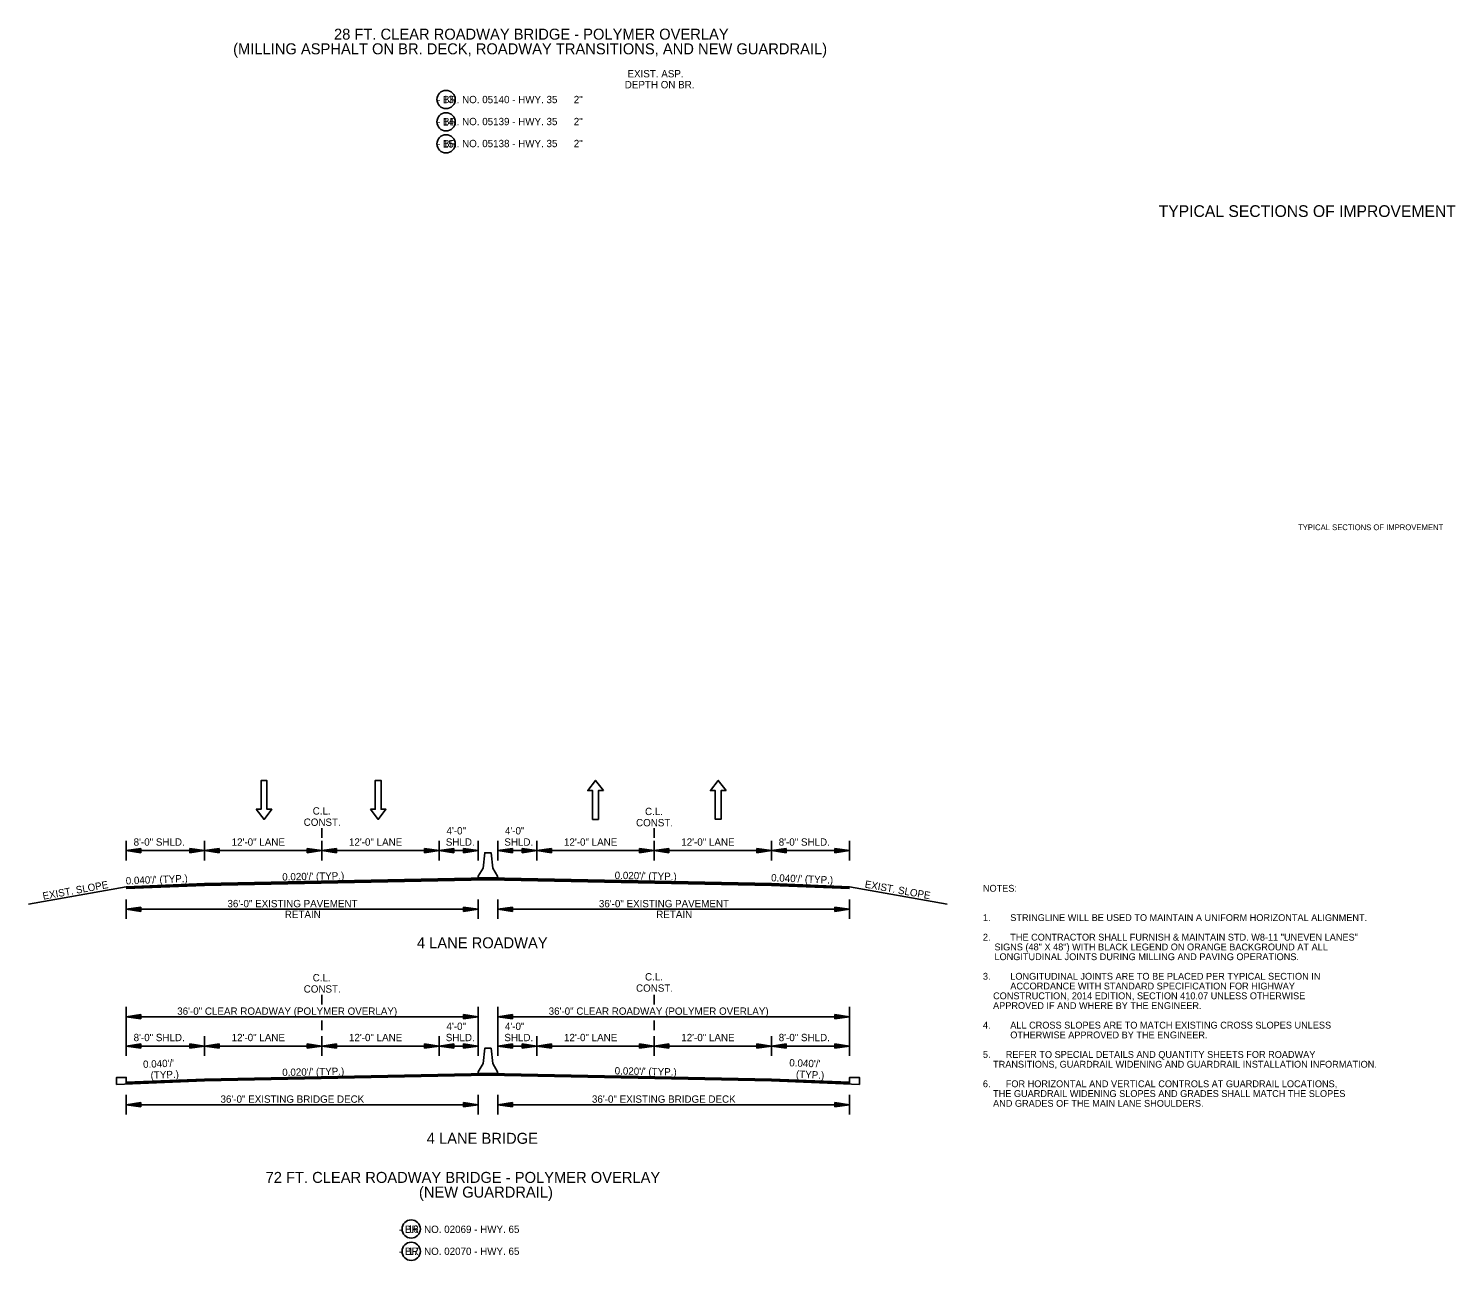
# Model space of a CAD drawing. Extents: x 545241 to 1930787, y -1971772 to 596640.
# Drawn here: x 546808 to 548268, y -1954639 to -1953379 of the extents above; entities that cross this region are included whole.
import ezdxf

# ---------------------------------------------------------------- set-up
doc = ezdxf.new("R2010")
doc.units = 0
for name, color, linetype in [('Default', 7, 'Continuous'), ('R_Border', 7, 'Continuous'), ('R_Border Notes', 7, 'Continuous'), ('R_Border Prem', 7, 'Continuous'), ('R_Draft', 7, 'Continuous')]:
    doc.layers.add(name, color=color, linetype=linetype)

# ---------------------------------------------------------------- blocks, each defined once
blk = doc.blocks.new('ARROW')
at = {"layer": 'R_Draft'}
for p, q in [((-2, 0.3), (0, 0)), ((-2, 0.3), (-2, -0.3)), ((-2, 0.25), (-0.334, 0)), ((-2, 0.199), (-0.678, 0)), ((-2, 0.149), (-1.011, 0)), ((-2, 0.097), (-1.35, 0)), ((-2, 0.047), (-1.684, 0)), ((-2, -0.3), (0, 0)), ((-2, -0.098), (-1.35, 0)), ((-2, -0.199), (-0.678, 0)), ((-2, -0.25), (-0.334, 0)), ((-2, -0.149), (-1.011, 0)), ((-2, -0.047), (-1.684, 0))]:
    blk.add_line(p, q, dxfattribs=at)
blk = doc.blocks.new('MedBarrier')
at = {"layer": 'Default'}
blk.add_lwpolyline([(-10, 0), (-9.9, 1.7), (-5, 10), (-3.3, 25.8), (3.3, 25.8), (5, 10), (9.9, 1.7), (10, 0)], close=True, dxfattribs=at)

msp = doc.modelspace()

# ---------------------------------------------------------------- linework, layer by layer
at = {"layer": 'R_Border'}
for p, q in [((547108, -1954196.8), (547108, -1954206.8)), ((547448, -1954196.8), (547448, -1954206.8)), ((546908, -1954209.8), (546908, -1954229.8)), ((546988, -1954209.8), (546988, -1954229.8)), ((547108, -1954209.8), (547108, -1954229.8)), ((547228, -1954209.8), (547228, -1954229.8)), ((547268, -1954209.8), (547268, -1954229.8)), ((547288, -1954209.8), (547288, -1954229.8)), ((547328, -1954209.8), (547328, -1954229.8)), ((547448, -1954209.8), (547448, -1954229.8)), ((547568, -1954209.8), (547568, -1954229.8)), ((547648, -1954209.8), (547648, -1954229.8)), ((546908, -1954219.8), (547268, -1954219.8)), ((547288, -1954219.8), (547648, -1954219.8)), ((546908, -1954256.8), (546808, -1954274.8)), ((547648, -1954256.8), (547748, -1954274.8)), ((546908, -1954269.8), (546908, -1954289.8)), ((547268, -1954269.8), (547268, -1954289.8)), ((547288, -1954269.8), (547288, -1954289.8)), ((547648, -1954269.8), (547648, -1954289.8)), ((546908, -1954279.8), (547268, -1954279.8)), ((547288, -1954279.8), (547648, -1954279.8)), ((547108, -1954367.3), (547108, -1954377.3)), ((547448, -1954367.3), (547448, -1954377.3)), ((546908, -1954379.8), (546908, -1954429.8)), ((546908, -1954389.8), (547268, -1954389.8)), ((547268, -1954379.8), (547268, -1954429.8)), ((547288, -1954379.8), (547288, -1954429.8)), ((547288, -1954389.8), (547648, -1954389.8)), ((547648, -1954379.8), (547648, -1954429.8)), ((547108, -1954393.5), (547108, -1954403.6)), ((547448, -1954393.5), (547448, -1954403.6)), ((546908, -1954419.8), (547268, -1954419.8)), ((546988, -1954409.8), (546988, -1954429.8)), ((547108, -1954409.8), (547108, -1954429.8)), ((547228, -1954409.8), (547228, -1954429.8)), ((547288, -1954419.8), (547648, -1954419.8)), ((547328, -1954409.8), (547328, -1954429.8)), ((547448, -1954409.8), (547448, -1954429.8)), ((547568, -1954409.8), (547568, -1954429.8)), ((546908, -1954469.8), (546908, -1954489.8)), ((546908, -1954469.8), (546908, -1954489.8)), ((547268, -1954469.8), (547268, -1954489.8)), ((547288, -1954469.8), (547288, -1954489.8)), ((547648, -1954469.8), (547648, -1954489.8)), ((547648, -1954469.8), (547648, -1954489.8)), ((546908, -1954479.8), (547268, -1954479.8)), ((547288, -1954479.8), (547648, -1954479.8))]:
    msp.add_line(p, q, dxfattribs=at)
for points in [[(547040.9, -1954177.6), (547048.9, -1954188), (547056.9, -1954177.6), (547051.9, -1954177.6), (547051.9, -1954148.2), (547045.9, -1954148.2), (547045.9, -1954177.6)], [(547157.7, -1954177.6), (547165.7, -1954187.9), (547173.7, -1954177.6), (547168.7, -1954177.6), (547168.7, -1954148.1), (547162.7, -1954148.1), (547162.7, -1954177.6)], [(547396.1, -1954158.5), (547388.1, -1954148.1), (547380.1, -1954158.5), (547385.1, -1954158.5), (547385.1, -1954187.9), (547391.1, -1954187.9), (547391.1, -1954158.5)], [(547521.6, -1954158.4), (547513.6, -1954148), (547505.6, -1954158.4), (547510.6, -1954158.4), (547510.6, -1954187.8), (547516.6, -1954187.8), (547516.6, -1954158.4)]]:
    msp.add_lwpolyline(points, close=True, dxfattribs=at)
for points in [[(546908, -1954256.8), (546988, -1954253.6), (547278, -1954247.8), (547568, -1954253.6), (547648, -1954256.8)], [(546908, -1954257.1), (546988, -1954253.9), (547278, -1954248.1), (547568, -1954253.9), (547648, -1954257.1)], [(546908, -1954257.4), (546988, -1954254.2), (547278, -1954248.4), (547568, -1954254.2), (547648, -1954257.4)], [(546908, -1954257.7), (546988, -1954254.5), (547278, -1954248.7), (547568, -1954254.5), (547648, -1954257.7)], [(546908, -1954258), (546988, -1954254.8), (547278, -1954249), (547568, -1954254.8), (547648, -1954258)], [(546908, -1954258.3), (546988, -1954255.1), (547278, -1954249.3), (547568, -1954255.1), (547648, -1954258.3)], [(546908, -1954258.6), (546988, -1954255.4), (547278, -1954249.6), (547568, -1954255.4), (547648, -1954258.6)], [(546908, -1954456.8), (546988, -1954453.6), (547278, -1954447.8), (547568, -1954453.6), (547648, -1954456.8)], [(546908, -1954457.1), (546988, -1954453.9), (547278, -1954448.1), (547568, -1954453.9), (547648, -1954457.1)], [(546908, -1954457.4), (546988, -1954454.2), (547278, -1954448.4), (547568, -1954454.2), (547648, -1954457.4)], [(546908, -1954457.7), (546988, -1954454.5), (547278, -1954448.7), (547568, -1954454.5), (547648, -1954457.7)], [(546908, -1954458), (546988, -1954454.8), (547278, -1954449), (547568, -1954454.8), (547648, -1954458)], [(546908, -1954458.3), (546988, -1954455.1), (547278, -1954449.3), (547568, -1954455.1), (547648, -1954458.3)], [(546898, -1954459), (546988, -1954455.4), (547278, -1954449.6), (547568, -1954455.4), (547658, -1954459)], [(546908, -1954458.3), (546908, -1954451.8), (546898, -1954451.8), (546898, -1954459)], [(547648, -1954459), (547648, -1954451.8), (547658, -1954451.8), (547658, -1954459)]]:
    msp.add_lwpolyline(points, dxfattribs=at)
for centre in [(547235.2, -1953451.4), (547235.2, -1953474.3), (547235.2, -1953496.8), (547199.5, -1954607), (547199.5, -1954629.8)]:
    msp.add_circle(centre, 9.34, dxfattribs=at)

# ---------------------------------------------------------------- block references
at = {"layer": 'R_Border', "xscale": 7.5, "yscale": 7.5, "rotation": 180}
for p in [(546908, -1954219.8), (546988, -1954219.8), (546988, -1954219.8), (547108, -1954219.8), (547228, -1954219.8), (547288, -1954219.8), (547328, -1954219.8), (547448, -1954219.8), (547568, -1954219.8), (546908, -1954279.8), (547288, -1954279.8), (546908, -1954389.8), (547288, -1954389.8), (546908, -1954419.8), (546988, -1954419.8), (546988, -1954419.8), (547108, -1954419.8), (547228, -1954419.8), (547288, -1954419.8), (547328, -1954419.8), (547448, -1954419.8), (547568, -1954419.8), (546908, -1954479.8), (546908, -1954479.8), (547288, -1954479.8)]:
    msp.add_blockref('ARROW', p, dxfattribs=at)
at = {"layer": 'R_Border', "xscale": 7.5, "yscale": 7.5}
for p in [(546988, -1954219.8), (547108, -1954219.8), (547228, -1954219.8), (547268, -1954219.8), (547328, -1954219.8), (547448, -1954219.8), (547568, -1954219.8), (547648, -1954219.8), (547268, -1954279.8), (547648, -1954279.8), (547268, -1954389.8), (547648, -1954389.8), (546988, -1954419.8), (547108, -1954419.8), (547228, -1954419.8), (547268, -1954419.8), (547328, -1954419.8), (547448, -1954419.8), (547568, -1954419.8), (547648, -1954419.8), (547268, -1954479.8), (547648, -1954479.8), (547648, -1954479.8)]:
    msp.add_blockref('ARROW', p, dxfattribs=at)
at = {"layer": 'R_Draft', "rotation": 0.0005105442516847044}
for p in [(547278, -1954247.8), (547278, -1954447.8)]:
    msp.add_blockref('MedBarrier', p, dxfattribs=at)

# ---------------------------------------------------------------- texts
at = {"layer": 'R_Border'}
for s, height, p in [('28 FT. CLEAR ROADWAY BRIDGE - POLYMER OVERLAY', 11.25, (547120.5, -1953390.2)), ('(MILLING ASPHALT ON BR. DECK, ROADWAY TRANSITIONS, AND NEW GUARDRAIL)', 11.25, (547017.3, -1953405.2)), ('13', 7.5, (547231.9, -1953455.1)), ('14', 7.5, (547231.9, -1953478.1)), ('15', 7.5, (547231.9, -1953500.6)), ('C.L.', 7.5, (547098.7, -1954183)), ('C.L.', 7.5, (547438.7, -1954183.5)), ('CONST.', 7.5, (547089.5, -1954194.5)), ('4\'-0"', 7.5, (547235.6, -1954203.3)), ('4\'-0"', 7.5, (547295.4, -1954203.3)), ('CONST.', 7.5, (547429.5, -1954195)), ('8\'-0" SHLD.', 7.5, (546915.5, -1954214.8)), ('12\'-0" LANE', 7.5, (547015.8, -1954214.8)), ('12\'-0" LANE', 7.5, (547135.8, -1954214.8)), ('SHLD.', 7.5, (547234.9, -1954214.8)), ('SHLD.', 7.5, (547294.8, -1954214.8)), ('12\'-0" LANE', 7.5, (547355.8, -1954214.8)), ('12\'-0" LANE', 7.5, (547475.8, -1954214.8)), ('8\'-0" SHLD.', 7.5, (547575.5, -1954214.8)), ('36\'-0" EXISTING PAVEMENT', 7.5, (547011.5, -1954277.8)), ('36\'-0" EXISTING PAVEMENT', 7.5, (547391.5, -1954277.8)), ('RETAIN', 7.5, (547070.2, -1954288.8)), ('RETAIN', 7.5, (547450.2, -1954288.8)), ('4 LANE ROADWAY', 11.25, (547205.3, -1954319.8)), ('C.L.', 7.5, (547098.7, -1954353.6)), ('C.L.', 7.5, (547438.7, -1954352.7)), ('CONST.', 7.5, (547089.5, -1954365.1)), ('CONST.', 7.5, (547429.5, -1954364.2)), ('36\'-0" CLEAR ROADWAY (POLYMER OVERLAY)', 7.5, (546960.1, -1954387.8)), ('36\'-0" CLEAR ROADWAY (POLYMER OVERLAY)', 7.5, (547340.1, -1954387.8)), ('4\'-0"', 7.5, (547235.6, -1954403.3)), ('4\'-0"', 7.5, (547295.4, -1954403.3)), ('8\'-0" SHLD.', 7.5, (546915.5, -1954414.8)), ('12\'-0" LANE', 7.5, (547015.8, -1954414.8)), ('12\'-0" LANE', 7.5, (547135.8, -1954414.8)), ('SHLD.', 7.5, (547234.9, -1954414.8)), ('SHLD.', 7.5, (547294.8, -1954414.8)), ('12\'-0" LANE', 7.5, (547355.8, -1954414.8)), ('12\'-0" LANE', 7.5, (547475.8, -1954414.8)), ('8\'-0" SHLD.', 7.5, (547575.5, -1954414.8)), ('36\'-0" EXISTING BRIDGE DECK', 7.5, (547004.4, -1954477.8)), ('36\'-0" EXISTING BRIDGE DECK', 7.5, (547384.4, -1954477.8)), ('4 LANE BRIDGE', 11.25, (547215.4, -1954519.8)), ('72 FT. CLEAR ROADWAY BRIDGE - POLYMER OVERLAY', 11.25, (547050.5, -1954559.8)), ('(NEW GUARDRAIL)', 11.25, (547207.4, -1954574.8)), ('16', 7.5, (547195.9, -1954610.7)), ('17', 7.5, (547196.1, -1954633.5))]:
    msp.add_text(s, height=height, dxfattribs=at).set_placement(p)
for s, height, rotation, p in [('TYPICAL SECTIONS OF IMPROVEMENT', 12, 360, (547964.2, -1953571.6)), ("0.040'/' (TYP.)", 7.5, 2.2916, (546907.6, -1954254.5)), ("0.020'/' (TYP.)", 7.5, 1.1458, (547067.6, -1954250.5)), ("0.020'/' (TYP.)", 7.5, 358.8542, (547407.6, -1954248.8)), ("0.040'/' (TYP.)", 7.5, 357.7084, (547567.6, -1954251.2)), ('EXIST. SLOPE', 7.5, 10.204, (546823.1, -1954270.1)), ('EXIST. SLOPE', 7.5, 349.796, (547663.1, -1954257.6)), ("0.040'/'", 7.5, 2.2916, (546925.3, -1954442.2)), ("0.040'/'", 7.5, 357.7084, (547586.2, -1954440.5)), ('(TYP.)', 7.5, 2.2916, (546933, -1954453.4)), ("0.020'/' (TYP.)", 7.5, 1.1458, (547067.6, -1954450.5)), ("0.020'/' (TYP.)", 7.5, 358.8542, (547407.6, -1954448.8)), ('(TYP.)', 7.5, 357.7084, (547593, -1954452.2))]:
    msp.add_text(s, height=height, rotation=rotation, dxfattribs=at).set_placement(p)
at = {"layer": 'R_Border Notes'}
for s, p in [('NOTES: ', (547784.4, -1954261.9)), ('1.', (547784.4, -1954291.9)), ('STRINGLINE WILL BE USED TO MAINTAIN A UNIFORM HORIZONTAL ALIGNMENT.', (547812.4, -1954291.9)), ('2.', (547784.4, -1954311.9)), ('    SIGNS (48" X 48") WITH BLACK LEGEND ON ORANGE BACKGROUND AT ALL ', (547785.8, -1954321.9)), ('THE CONTRACTOR SHALL FURNISH & MAINTAIN STD. W8-11 "UNEVEN LANES" ', (547812.4, -1954311.9)), ('    LONGITUDINAL JOINTS DURING MILLING AND PAVING OPERATIONS.', (547785.8, -1954331.9)), ('3.', (547784.4, -1954351.9)), ('LONGITUDINAL JOINTS ARE TO BE PLACED PER TYPICAL SECTION IN ', (547812.4, -1954351.9)), ('ACCORDANCE WITH STANDARD SPECIFICATION FOR HIGHWAY', (547812.4, -1954361.9)), ('    APPROVED IF AND WHERE BY THE ENGINEER.', (547784.4, -1954381.9)), ('    CONSTRUCTION, 2014 EDITION, SECTION 410.07 UNLESS OTHERWISE', (547784.4, -1954371.9)), ('4.', (547784.4, -1954401.9)), ('ALL CROSS SLOPES ARE TO MATCH EXISTING CROSS SLOPES UNLESS ', (547812.4, -1954401.9)), ('OTHERWISE APPROVED BY THE ENGINEER.', (547812.4, -1954411.9)), ('5.      REFER TO SPECIAL DETAILS AND QUANTITY SHEETS FOR ROADWAY', (547784.4, -1954431.9)), ('    TRANSITIONS, GUARDRAIL WIDENING AND GUARDRAIL INSTALLATION INFORMATION.', (547784.4, -1954441.9)), ('6.      FOR HORIZONTAL AND VERTICAL CONTROLS AT GUARDRAIL LOCATIONS,', (547784.4, -1954461.9)), ('    AND GRADES OF THE MAIN LANE SHOULDERS.  ', (547784.4, -1954481.9)), ('    THE GUARDRAIL WIDENING SLOPES AND GRADES SHALL MATCH THE SLOPES', (547784.4, -1954471.9))]:
    msp.add_text(s, height=7, dxfattribs=at).set_placement(p)
at = {"layer": 'R_Border Prem'}
msp.add_text('TYPICAL SECTIONS OF IMPROVEMENT', height=5.862, rotation=360, dxfattribs=at).set_placement((548106.8, -1953892))
at = {"layer": 'R_Draft'}
for s, p in [(' EXIST. ASP. ', (547418, -1953428.8)), ('DEPTH ON BR. ', (547418, -1953440)), ('      - BR. NO. 05140 - HWY. 35      2"', (547209.2, -1953455.2)), ('      - BR. NO. 05139 - HWY. 35      2"', (547209.2, -1953477.7)), ('      - BR. NO. 05138 - HWY. 35      2"', (547209.2, -1953500.2)), ('       - BR. NO. 02069 - HWY. 65      ', (547167.5, -1954611)), ('       - BR. NO. 02070 - HWY. 65', (547167.5, -1954633.5))]:
    msp.add_text(s, height=7.5, dxfattribs=at).set_placement(p)

doc.saveas('drawing.dxf')
